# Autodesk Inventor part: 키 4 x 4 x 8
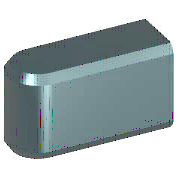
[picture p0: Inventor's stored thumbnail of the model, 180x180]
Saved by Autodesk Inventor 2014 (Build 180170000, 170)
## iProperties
Created: 2012-02
Part Number: 키 4 x 4 x 8
Material: 강철, 연강
Description: 키 및 해당 키홈
Document SubType Name: Modeling
Standard: KS B 1311
Designer: mduedu
Standards Organization: KS
Language: ko-KR
Size Designation: 4 x 4 x 8
Categories: <MemberInstance><Categories><Category DisplayName="샤프트 부품" InternalName="7f7aeb1f-a693-4053-b835-cee3144e0d98" Mnemonic="SHFT"><Category DisplayName="키" Interna
Density: 1 g/cm^3
Appearance: 노란색
IsCustomPart: 1
Author: mduedu
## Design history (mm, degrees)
sketch "스케치1"
  geometry: L1 (2, 2)-(8, 2); L2 (8, 2)-(8, -2); L3 (8, -2)-(2, -2); L4 (0, 7)-(0, -7) reference; L5 (-5, 0)-(30, 0) reference; A1 r 2 centre (2, 0) between (2, 2) and (2, -2)
  constraints: 6 end point, 3 tangent, 2 point on circle, 1 centre point, 1 horizontal, 1 parallel, 1 perpendicular, 1 point on line
  dimensions: "d0" = 2 radius of A1 (= 0.5 x PB); "d7" = 8 distance between parallel lines of L2 L4 (= NLG)
workplane "Work Plane1"
workplane "Work Plane2"
extrude "본체1" new body sketch "스케치1" taper "d3" = 0 deg; stored distance "d4" = 10
workaxis "Work Axis1"
workplane "Work Plane4"
body "Solid1"
chamfer "모따기1" distance "d8" = 0.25 (= PHH); stored, may be unused: second distance "d9" = 0.25 (= PHH), angle "d13" = 45 deg
other parameters: "d1" = -2.5 (= -PNT), "d2" = 1.5 (= PH - PNT), "NLG" = 8 [user parameter; used in 2 equation terms], "PB" = 4 [user parameter; used in 1 equation term], "PNT" = 2.5 [user parameter; used in 2 equation terms], "PH" = 4 [user parameter; used in 1 equation term], "PHH" = 0.25 [user parameter; used in 2 equation terms], "d10" = 0, "d16" = 0, "d17" = 0, "d18" = 0, "RR" = 0.08 [user parameter], "WDMAX" = 12 [user parameter], "PLB1" = 8 (= NLG) [user parameter], "PUEB" = 1.8 [user parameter]
